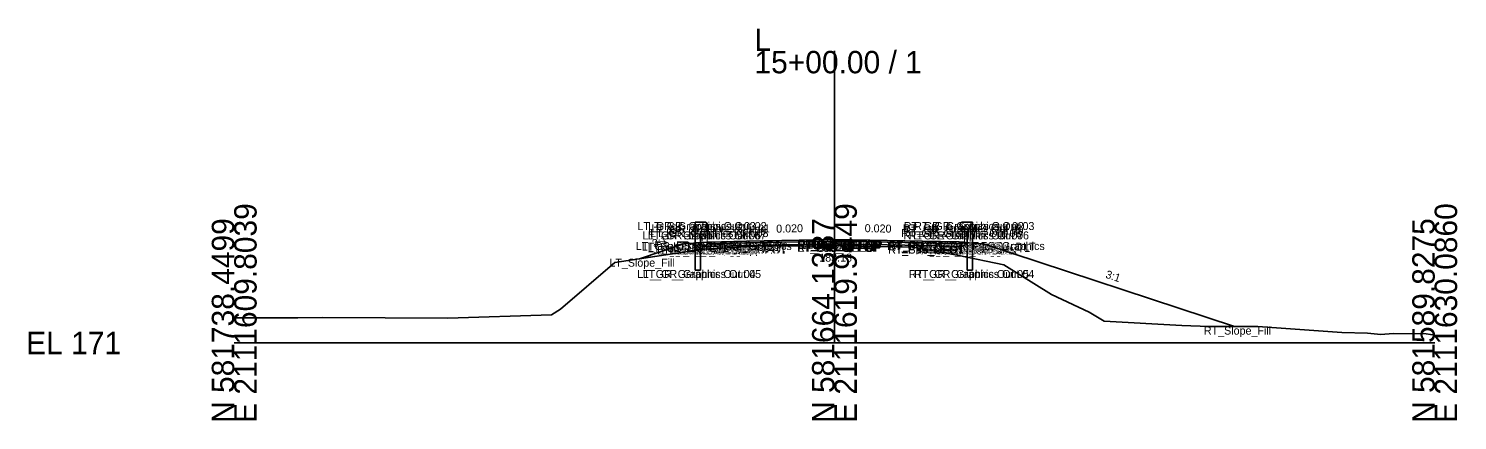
# Model space of a CAD drawing. Extents: x -486 to 1153, y -333 to 9539.
# Drawn here: x -25.7 to 152.8, y 5490.3 to 5539.3 of the extents above; entities that cross this region are included whole.
import ezdxf

# ---------------------------------------------------------------- set-up
doc = ezdxf.new("R2010")
doc.units = 0
for name, color, linetype in [('Default', 7, 'Continuous'), ('Exist Cross Section Cell', 7, 'Continuous'), ('Exist XS Ground Line', 7, 'Continuous'), ('Prop CMT Guardrail Graphics', 7, 'Continuous'), ('Prop CMT Pvmt Course 1', 7, 'Continuous'), ('Prop CMT Pvmt Course 2', 7, 'Continuous'), ('Prop CMT Pvmt Course 3', 7, 'Continuous'), ('Prop CMT Pvmt Surface', 7, 'Continuous'), ('Prop CMT Pvmt Surface Shoulder', 7, 'Continuous'), ('Prop CMT Shld Paved Course 1', 7, 'Continuous'), ('Prop CMT Shld Paved Course 2', 7, 'Continuous'), ('Prop CMT Shld Paved Course 3', 7, 'Continuous'), ('Prop CMT Slope Grass', 7, 'Continuous'), ('Prop CMT Subgrade Earthwork', 7, 'Continuous'), ('Prop XS Earthwork Shape', 7, 'Continuous'), ('Prop XS SE Text', 7, 'Continuous'), ('Prop XS Side Slope Text', 7, 'Continuous'), ('Scratch_Level_0', 7, 'Continuous')]:
    doc.layers.add(name, color=color, linetype=linetype)

msp = doc.modelspace()

# ---------------------------------------------------------------- linework, layer by layer
at = {"layer": 'Exist Cross Section Cell'}
for p, q in [((75, 5500), (75, 5536.54)), ((0, 5500), (75, 5500)), ((75, 5500), (150, 5500))]:
    msp.add_line(p, q, dxfattribs=at)
at = {"layer": 'Exist XS Ground Line'}
for p, q in [((47.57, 5510.09), (57.21, 5511.54)), ((57.21, 5511.54), (58.81, 5511.73)), ((58.81, 5511.73), (65.21, 5512.13)), ((65.21, 5512.13), (73.41, 5512.17)), ((73.41, 5512.17), (74.81, 5512.18)), ((74.81, 5512.18), (76.25, 5512.15)), ((76.25, 5512.15), (84.84, 5511.99)), ((84.84, 5511.99), (88.49, 5511.31)), ((88.49, 5511.31), (90.54, 5510.96)), ((40.79, 5504.24), (47.57, 5510.09)), ((90.54, 5510.96), (96.15, 5509.77)), ((96.15, 5509.77), (102.1, 5506.08)), ((102.1, 5506.08), (106.81, 5503.84)), ((39.65, 5503.54), (40.79, 5504.24)), ((0, 5503.15), (7.95, 5503.16)), ((7.95, 5503.16), (11.02, 5503.21)), ((11.02, 5503.21), (26.68, 5503.09)), ((26.68, 5503.09), (39.65, 5503.54)), ((106.81, 5503.84), (108.68, 5502.71)), ((108.68, 5502.71), (118.42, 5502.18)), ((118.42, 5502.18), (121.84, 5502.05)), ((121.84, 5502.05), (127.92, 5502.05)), ((127.92, 5502.05), (138.4, 5501.33)), ((138.4, 5501.33), (141.62, 5501.24)), ((141.62, 5501.24), (143.28, 5501.08)), ((143.28, 5501.08), (144.83, 5501.17)), ((144.83, 5501.17), (148.94, 5501.16)), ((148.94, 5501.16), (150, 5500.98))]:
    msp.add_line(p, q, dxfattribs=at)
at = {"layer": 'Prop CMT Guardrail Graphics'}
for points in [[(57.59, 5509.13), (57.59, 5515.13)], [(57.59, 5515.13), (58.92, 5515.13), (59.2, 5514.83)], [(92.24, 5515.13), (90.91, 5515.13), (90.64, 5514.84)], [(92.24, 5509.13), (92.24, 5515.13)], [(59.2, 5514.25), (58.92, 5513.96), (58.26, 5513.96)], [(58.26, 5513.96), (58.26, 5509.13)], [(59.2, 5514.83), (58.92, 5514.54)], [(58.92, 5514.54), (59.2, 5514.25)], [(90.64, 5514.84), (90.91, 5514.55)], [(90.91, 5514.55), (90.64, 5514.25)], [(90.64, 5514.25), (90.91, 5513.96), (91.58, 5513.96)], [(91.58, 5513.96), (91.58, 5509.13)], [(58.26, 5509.13), (57.59, 5509.13)], [(91.58, 5509.13), (92.24, 5509.13)]]:
    msp.add_lwpolyline(points, dxfattribs=at)
at = {"layer": 'Prop CMT Pvmt Course 1'}
for points in [[(75, 5512.95), (64, 5512.73)], [(64, 5512.52), (75, 5512.74)], [(64, 5512.73), (64, 5512.52)], [(75, 5512.74), (75, 5512.95)], [(75, 5512.95), (86, 5512.73)], [(75, 5512.74), (75, 5512.95)], [(86, 5512.52), (75, 5512.74)], [(86, 5512.73), (86, 5512.52)]]:
    msp.add_lwpolyline(points, dxfattribs=at)
msp.add_lwpolyline([(75, 5512.74), (75, 5512.82), (75, 5512.82), (75, 5512.74)], close=True, dxfattribs=at)
msp.add_lwpolyline([(75, 5512.74), (75, 5512.82), (75, 5512.82), (75, 5512.74)], close=True, dxfattribs=at)
at = {"layer": 'Prop CMT Pvmt Course 2'}
for points in [[(75, 5512.74), (64, 5512.52)], [(64, 5512.52), (64, 5512.19)], [(64, 5512.19), (75, 5512.41)], [(75, 5512.41), (75, 5512.74)], [(75, 5512.41), (75, 5512.74)], [(75, 5512.74), (86, 5512.52)], [(86, 5512.19), (75, 5512.41)], [(86, 5512.52), (86, 5512.19)]]:
    msp.add_lwpolyline(points, dxfattribs=at)
at = {"layer": 'Prop CMT Pvmt Course 3'}
for points in [[(75, 5512.41), (64, 5512.19)], [(64, 5512.19), (64, 5512.19)], [(75, 5512.41), (75, 5512.41)], [(75, 5512.41), (86, 5512.19)], [(75, 5512.41), (75, 5512.41)], [(86, 5512.19), (86, 5512.19)]]:
    msp.add_lwpolyline(points, dxfattribs=at)
at = {"layer": 'Prop CMT Pvmt Surface'}
for points in [[(75, 5512.95), (64, 5512.73)], [(75, 5512.95), (86, 5512.73)]]:
    msp.add_lwpolyline(points, dxfattribs=at)
at = {"layer": 'Prop CMT Pvmt Surface Shoulder'}
for points in [[(64, 5512.73), (59.3, 5512.63)], [(86, 5512.73), (90.54, 5512.64)]]:
    msp.add_lwpolyline(points, dxfattribs=at)
at = {"layer": 'Prop CMT Shld Paved Course 1'}
for points in [[(64, 5512.73), (59.3, 5512.63), (59.08, 5512.42)], [(59.08, 5512.42), (64, 5512.52)], [(64, 5512.52), (64, 5512.73)], [(86, 5512.73), (90.54, 5512.64), (90.75, 5512.42)], [(86, 5512.52), (86, 5512.73)], [(90.75, 5512.42), (86, 5512.52)]]:
    msp.add_lwpolyline(points, dxfattribs=at)
at = {"layer": 'Prop CMT Shld Paved Course 2'}
for points in [[(64, 5512.52), (59.08, 5512.42), (58.74, 5512.08)], [(58.74, 5512.08), (64, 5512.19)], [(64, 5512.19), (64, 5512.52)], [(86, 5512.52), (90.75, 5512.42), (91.09, 5512.08)], [(86, 5512.19), (86, 5512.52)], [(91.09, 5512.08), (86, 5512.19)]]:
    msp.add_lwpolyline(points, dxfattribs=at)
at = {"layer": 'Prop CMT Shld Paved Course 3'}
for points in [[(64, 5512.19), (58.74, 5512.08)], [(58.74, 5512.08), (58.74, 5512.08), (58.74, 5512.08)], [(64, 5512.19), (64, 5512.19)], [(86, 5512.19), (91.09, 5512.08)], [(86, 5512.19), (86, 5512.19)], [(91.09, 5512.08), (91.09, 5512.08), (91.09, 5512.08)]]:
    msp.add_lwpolyline(points, dxfattribs=at)
at = {"layer": 'Prop CMT Slope Grass'}
for points in [[(56.2, 5512.39), (50.64, 5510.55)], [(59.2, 5512.63), (56.2, 5512.39)], [(59.3, 5512.63), (59.2, 5512.63)], [(90.54, 5512.64), (90.64, 5512.63)], [(90.64, 5512.63), (93.64, 5512.39)], [(93.64, 5512.39), (124.98, 5502.05)]]:
    msp.add_lwpolyline(points, dxfattribs=at)
at = {"layer": 'Prop CMT Subgrade Earthwork'}
for points in [[(58.74, 5512.08), (58.27, 5512.55)], [(64, 5512.19), (58.74, 5512.08)], [(75, 5512.41), (64, 5512.19)], [(75, 5512.41), (86, 5512.19)], [(86, 5512.19), (91.09, 5512.08)], [(91.09, 5512.08), (91.56, 5512.55)]]:
    msp.add_lwpolyline(points, dxfattribs=at)
at = {"layer": 'Prop XS Earthwork Shape'}
msp.add_lwpolyline([(74.81, 5512.18), (76.25, 5512.15), (84.84, 5511.99), (88.49, 5511.31), (90.54, 5510.96), (96.15, 5509.77), (102.1, 5506.08), (106.81, 5503.84), (108.68, 5502.71), (118.42, 5502.18), (121.84, 5502.05), (124.98, 5502.05), (93.64, 5512.39), (91.56, 5512.55), (91.09, 5512.08), (86, 5512.19), (75, 5512.41), (64, 5512.19), (58.74, 5512.08), (58.27, 5512.55), (56.2, 5512.39), (50.64, 5510.55), (57.21, 5511.54), (58.81, 5511.73), (65.21, 5512.13), (73.41, 5512.17)], close=True, dxfattribs=at)

# ---------------------------------------------------------------- texts
at = {"layer": 'Default'}
for s, height, p in [('183.18', 1, (73.1, 5510.18)), ('-', 0.0001, (0, 5500))]:
    msp.add_text(s, height=height, dxfattribs=at).set_placement(p)
at = {"layer": 'Exist Cross Section Cell'}
for s, p in [('L', (65, 5536.54)), ('15+00.00 / 1', (65, 5533.74)), ('EL 171', (-26, 5498.6))]:
    msp.add_text(s, height=2.8, dxfattribs=at).set_placement(p)
for s, p in [('E 2111609.8039', (2.8, 5490)), ('E 2111619.9449', (77.8, 5490)), ('E 2111630.0860', (152.8, 5490)), ('N 581738.4499', (0, 5490)), ('N 581664.1387', (75, 5490)), ('N 581589.8275', (150, 5490))]:
    msp.add_text(s, height=2.8, rotation=90, dxfattribs=at).set_placement(p)
at = {"layer": 'Prop XS SE Text'}
for rotation, p in [(1.1458, (67.73, 5513.8)), (358.8542, (78.77, 5513.87))]:
    msp.add_text('0.020', height=1, rotation=rotation, dxfattribs=at).set_placement(p)
at = {"layer": 'Prop XS Side Slope Text'}
for rotation, p in [(18.2629, (52.43, 5511.93)), (341.7371, (108.79, 5508.18))]:
    msp.add_text('3:1', height=1, rotation=rotation, dxfattribs=at).set_placement(p)
at = {"layer": 'Scratch_Level_0'}
for s, p in [('LT_GR_Graphics Out 03', (50.38, 5514.13)), ('LT_GR_Graphics Out 02', (51.73, 5514.13)), ('LT_GR_Graphics Out 01', (52.14, 5513.83)), ('RT_GR_Graphics Out 01', (83.53, 5513.84)), ('RT_GR_Graphics Out 02', (83.65, 5514.13)), ('RT_GR_Graphics Out 03', (84.97, 5514.13)), ('LT_GR_Graphics Out 06', (51.03, 5512.96)), ('LT_GR_Graphics Out 07', (51.68, 5512.96)), ('LT_GR_Graphics Out 09', (51.7, 5513.54)), ('LT_GR_Graphics Out 08', (51.97, 5513.25)), ('RT_GR_Graphics Out 08', (83.35, 5513.25)), ('RT_GR_Graphics Out 07', (83.61, 5512.96)), ('RT_GR_Graphics Out 09', (83.63, 5513.55)), ('RT_GR_Graphics Out 06', (84.29, 5512.96)), ('LT_GS_OS_GR_Face_Graphics', (50.19, 5511.63)), ('LT_Sub_Trench_Out_DLT', (50.92, 5511.55)), ('LT_GS_OS_CTL', (51.66, 5511.39)), ('LT_Sub_Trench_Out', (52.85, 5511.08)), ('LT_PS3_Shelf_Out', (53.4, 5511.08)), ('LT_PS3_OEOP', (54.53, 5511.08)), ('LT_PS2_OEOP', (54.87, 5511.42)), ('LT_PS1_OEOP', (55.2, 5511.63)), ('LT_PV2_OEOT', (59.75, 5511.52)), ('LT_PV3_OEOT', (59.75, 5511.19)), ('LT_Sub_OEOT', (59.77, 5511.19)), ('LT_PV1_OEOT', (59.87, 5511.73)), ('RT_PV2_OEEOP', (70.33, 5511.74)), ('RT_PV3_OEEOP', (70.33, 5511.41)), ('RT_Sub_OEEOP', (70.36, 5511.41)), ('LT_PV2_OEEOP', (70.39, 5511.74)), ('LT_PV3_OEEOP', (70.39, 5511.41)), ('LT_Sub_OEEOP', (70.42, 5511.41)), ('RT_PV1_OEEOP', (70.45, 5511.82)), ('LT_PV1_OEEOP', (70.51, 5511.82)), ('RT_PV2_IEEOP', (70.71, 5511.74)), ('LT_PV2_IEEOP', (70.77, 5511.74)), ('RT_PV1_IEEOP', (70.83, 5511.82)), ('LT_PV1_IEEOP', (70.89, 5511.82)), ('PV2_PGL', (72.35, 5511.74)), ('PV1_PGL', (72.47, 5511.95)), ('RT_GS_OS_GR_Face_Graphics', (81.58, 5511.63)), ('RT_PV2_OEOT', (81.69, 5511.52)), ('RT_PV3_OEOT', (81.69, 5511.19)), ('RT_Sub_OEOT', (81.71, 5511.19)), ('RT_PV1_OEOT', (81.81, 5511.73)), ('RT_Sub_Trench_Out_DLT', (84.15, 5511.55)), ('RT_Sub_Trench_Out', (85.14, 5511.08)), ('RT_PS3_Shelf_Out', (85.69, 5511.08)), ('RT_PS1_OEOP', (86.39, 5511.64)), ('RT_PS2_OEOP', (86.48, 5511.42)), ('RT_PS3_OEOP', (86.82, 5511.08)), ('RT_GS_OS_CTL', (89.04, 5511.39)), ('LT_Slope_Fill', (46.88, 5509.55)), ('LT_GR_Graphics Out 04', (50.36, 5508.13)), ('LT_GR_Graphics Out 05', (51.04, 5508.13)), ('RT_GR_Graphics Out 05', (84.3, 5508.13)), ('RT_GR_Graphics Out 04', (84.95, 5508.13)), ('RT_Slope_Fill', (121.16, 5501.05))]:
    msp.add_text(s, height=1, dxfattribs=at).set_placement(p)

doc.saveas('drawing.dxf')
